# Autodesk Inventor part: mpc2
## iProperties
Shininess: 64.0
Length Units: 11269
Angle Units: 11279
Time Units: 11290
Mass Units: 11283
Length Display Precision: 3
Angle Display Precision: 2
Compacted: True
Part Number: mpc2
Document SubType Name: Modeling
Created: 2004-07
Designer: Peter
Manufacturer: Standard
Standards Organization: Custom
Density: 0.0
Volumn: 0.0
Area: 0.0
PropertySet Name: Model Information
Control State: 0
Master: False
Checked Out: False
Author: Peter
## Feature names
1. Extrusion1
2. Fillet1
3. Hole1
4. Sweep1
5. Extrusion2
6. Extrusion3
7. Extrusion4
8. Hole2
9. Extrusion5
10. Hole3
11. Hole4
